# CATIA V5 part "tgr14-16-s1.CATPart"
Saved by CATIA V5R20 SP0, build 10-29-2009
Part number: TGR14-16-S1
Revision: 1
Definition: design
Nomenclature: TGR14-16-S1
Source: made
Description: NOT SPECIFIED
Bounding box of the stored display mesh (mm): x -22 to 0.8, y 0 to 14, z -7 to 7
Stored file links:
  C:\Users\Raffaele\Desktop\3D X SITO CF\I-MOLD\TGR-S1\tgr14-s1.step\tgr14-16-s1.CATPart
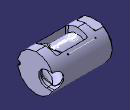
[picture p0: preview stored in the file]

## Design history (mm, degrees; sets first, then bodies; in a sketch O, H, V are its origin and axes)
Set1
  Line1 "LINE #4480": stored without definition
  DatumCurve1 "COMPOSITE_CURVE #4533"
  DatumCurve2 "COMPOSITE_CURVE #4584"
  DatumCurve3 "COMPOSITE_CURVE #4663"
  DatumCurve4 "COMPOSITE_CURVE #4706"
  DatumCurve5 "COMPOSITE_CURVE #4935"
  DatumCurve6 "COMPOSITE_CURVE #5076"
  DatumCurve7 "COMPOSITE_CURVE #5103"
  DatumCurve8 "COMPOSITE_CURVE #5161"
  DatumCurve9 "COMPOSITE_CURVE #5216"
  DatumCurve10 "COMPOSITE_CURVE #5245"
  DatumSurface1 "OPEN_SHELL #4470"
Body1 "MANIFOLD_SOLID_BREP #4471" (main body)
  Solid1: solid without history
